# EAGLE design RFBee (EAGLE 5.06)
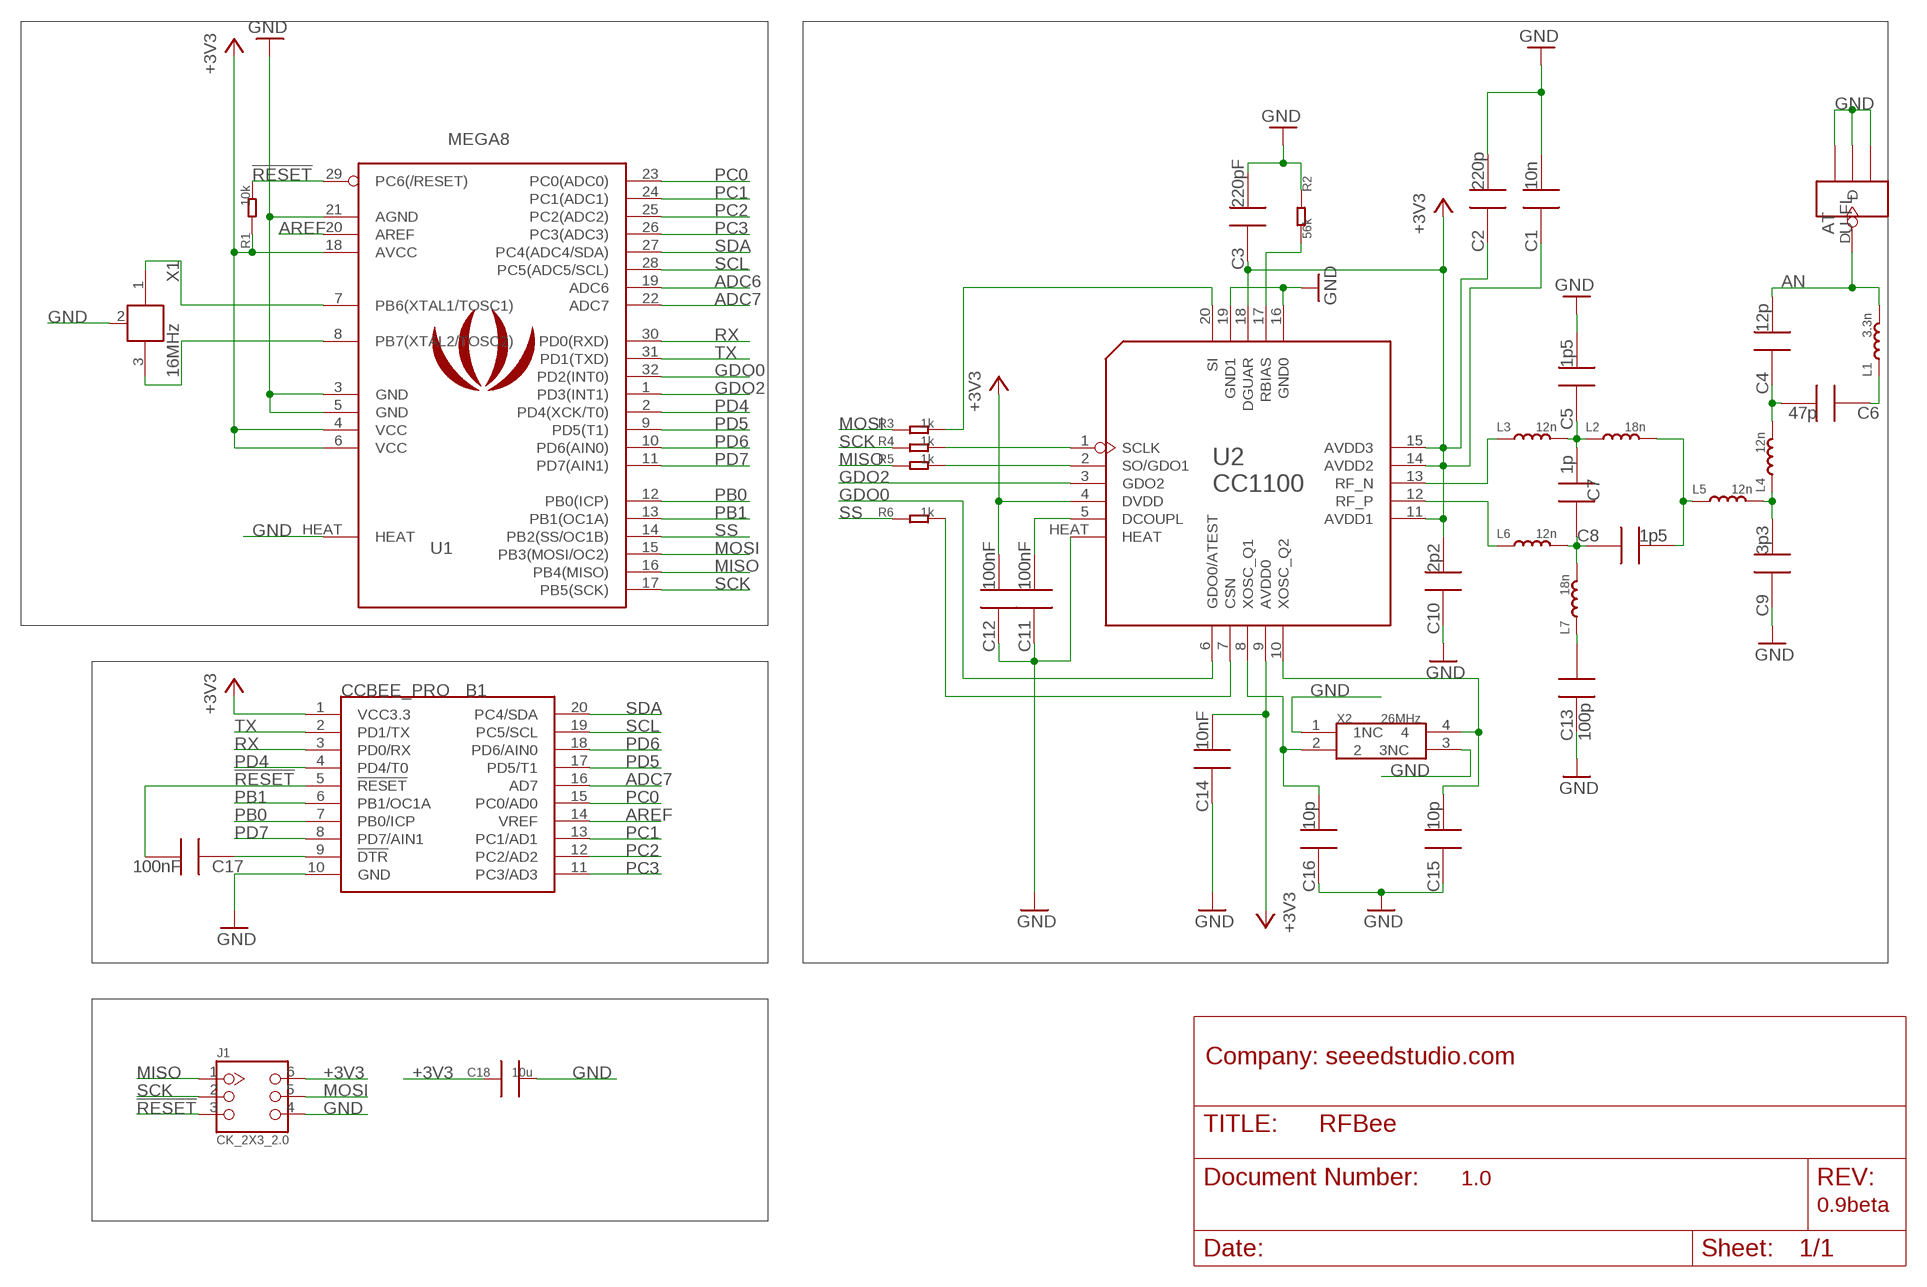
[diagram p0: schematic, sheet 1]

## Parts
AT  U-FL  [U-FL]
B1  CCBEE_PRO  [CCBEE-PRO]
C1  10n  C0603_S  [0603_S]
C2  220p  C0603_S  [0603_S]
C3  220pF  C0603_S  [0603_S]
C4  12p  C0603_S  [0603_S]
C5  1p5  C0603_S  [0603_S]
C6  47p  C0603_S  [0603_S]
C7  1p  C0603_S  [0603_S]
C8  1p5  C0603_S  [0603_S]
C9  3p3  C0603_S  [0603_S]
C10  2p2  C0603_S  [0603_S]
C11  100nF  C0603_S  [0603_S]
C12  100nF  C0603_S  [0603_S]
C13  100p  C0603_S  [0603_S]
C14  10nF  C0603_S  [0603_S]
C15  10p  C0603_S  [0603_S]
C16  10p  C0603_S  [0603_S]
C17  100nF  C0603_S  [0603_S]
C18  10u  C0805  [0805]
J1  CK_2X3_2.0  [CK_2X3_2.0]
L1  3.3n  L0603_S  [0603_S]
L2  18n  L0603_S  [0603_S]
L3  12n  L0603_S  [0603_S]
L4  12n  L0603_S  [0603_S]
L5  12n  L0603_S  [0603_S]
L6  12n  L0603_S  [0603_S]
L7  18n  L0603_S  [0603_S]
LOGO1  LOGO_SILK  [LOGO_SILK]
R1  10k  R0603_S  [0603_S]
R2  56k  R0603_S  [0603_S]
R3  1k  R0603_S  [0603_S]
R4  1k  R0603_S  [0603_S]
R5  1k  R0603_S  [0603_S]
R6  1k  R0603_S  [0603_S]
U1  MEGA8  [MLF32X]
U2  CC1100  [QFN20]
X1  16MHz  XTAL_NCVER  [XTAL_3X2]
X2  26MHz  XTAL_SMD_3225  [X3225]

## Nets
!RESET: B1.5(!RESET) C17.2 J1.3 R1.2 U1.29(PC6(/RESET))
+3V3: B1.1(VCC3.3) C1.1 C2.1 C3.1 C10.2 C12.2 C14.2 C18.1 J1.6 R1.1 U1.4(VCC) U1.6(VCC) U1.18(AVCC) U2.4(DVDD) U2.9(AVDD0) U2.11(AVDD1) U2.14(AVDD2) U2.15(AVDD3) U2.18(DGUAR)
ADC6: U1.19(ADC6)
ADC7: B1.16(AD7) U1.22(ADC7)
AN: AT.D C4.2 L1.2
AREF: B1.14(VREF) U1.20(AREF)
DTR: B1.9(!DTR) C17.1
GDO0: U1.32(PD2(INT0)) U2.6(GDO0/ATEST)
GDO2: U1.1(PD3(INT1)) U2.3(GDO2)
GND: AT.GND1 AT.GND2 AT.GND3 B1.10(GND) C1.2 C2.2 C3.2 C5.2 C9.1 C10.1 C11.1 C12.1 C13.1 C14.1 C15.1 C16.1 C18.2 J1.4 R2.1 U1.3(GND) U1.5(GND) U1.21(AGND) U1.HEAT U2.16(GND0) U2.19(GND1) U2.HEAT X1.2(GND) X2.1(1NC) X2.3(3NC)
MISO: J1.1 R5.1 U1.16(PB4(MISO))
MOSI: J1.5 R3.1 U1.15(PB3(MOSI/OC2))
N$1: C11.2 U2.5(DCOUPL)
N$2: C16.2 U2.8(XOSC_Q1) X2.2
N$3: R4.2 U2.1(SCLK)
N$4: L3.1 U2.13(RF_N)
N$5: L6.1 U2.12(RF_P)
N$6: C5.1 C7.2 L2.1 L3.2
N$7: C7.1 C8.1 L6.2 L7.2
N$8: C8.2 L2.2 L5.1
N$9: C9.2 L4.1 L5.2
N$10: C4.1 C6.2 L4.2
N$11: U1.7(PB6(XTAL1/TOSC1)) X1.1
N$12: C13.2 L7.1
N$13: U1.8(PB7(XTAL2/TOSC2)) X1.3
N$14: R3.2 U2.20(SI)
N$15: R2.2 U2.17(RBIAS)
N$16: C15.2 U2.10(XOSC_Q2) X2.4
N$17: R5.2 U2.2(SO/GDO1)
N$18: R6.2 U2.7(CSN)
N$21: C6.1 L1.1
PB0: B1.7(PB0/ICP) U1.12(PB0(ICP))
PB1: B1.6(PB1/OC1A) U1.13(PB1(OC1A))
PC0: B1.15(PC0/AD0) U1.23(PC0(ADC0))
PC1: B1.13(PC1/AD1) U1.24(PC1(ADC1))
PC2: B1.12(PC2/AD2) U1.25(PC2(ADC2))
PC3: B1.11(PC3/AD3) U1.26(PC3(ADC3))
PD4: B1.4(PD4/T0) U1.2(PD4(XCK/T0))
PD5: B1.17(PD5/T1) U1.9(PD5(T1))
PD6: B1.18(PD6/AIN0) U1.10(PD6(AIN0))
PD7: B1.8(PD7/AIN1) U1.11(PD7(AIN1))
RX: B1.3(PD0/RX) U1.30(PD0(RXD))
SCK: J1.2 R4.1 U1.17(PB5(SCK))
SCL: B1.19(PC5/SCL) U1.28(PC5(ADC5/SCL))
SDA: B1.20(PC4/SDA) U1.27(PC4(ADC4/SDA))
SS: R6.1 U1.14(PB2(SS/OC1B))
TX: B1.2(PD1/TX) U1.31(PD1(TXD))

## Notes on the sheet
- Company: seeedstudio.com
- 1.0
- 0.9beta

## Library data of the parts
AT = CPT_SMD:U-FL
B1 = EXT_moudle:CCBEE
C1-C17 = CPT_SMD:C0603
C18 = CPT_SMD:C0805
J1 = CONNECTER:CK_2X3
L1-L7 = CPT_SMD:L0603
LOGO1 = logo:LOGO_SILK
R1-R6 = CPT_SMD:R0603
U1 = ICs_v54:MEGA8
U2 = Wireless_chips:CC1100
X1 = CPT_SMD:XTAL_NC
X2 = CPT_SMD:XTAL_SMD

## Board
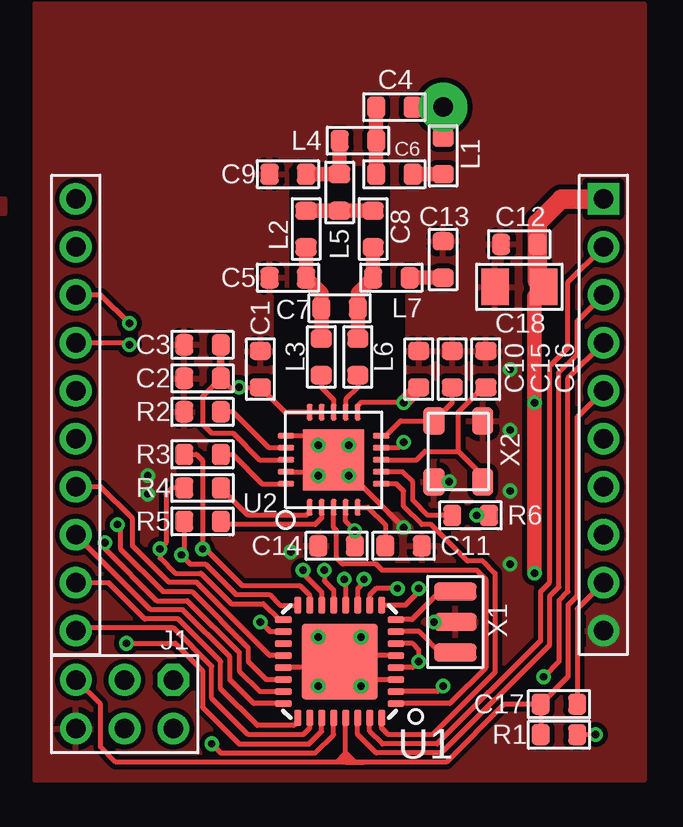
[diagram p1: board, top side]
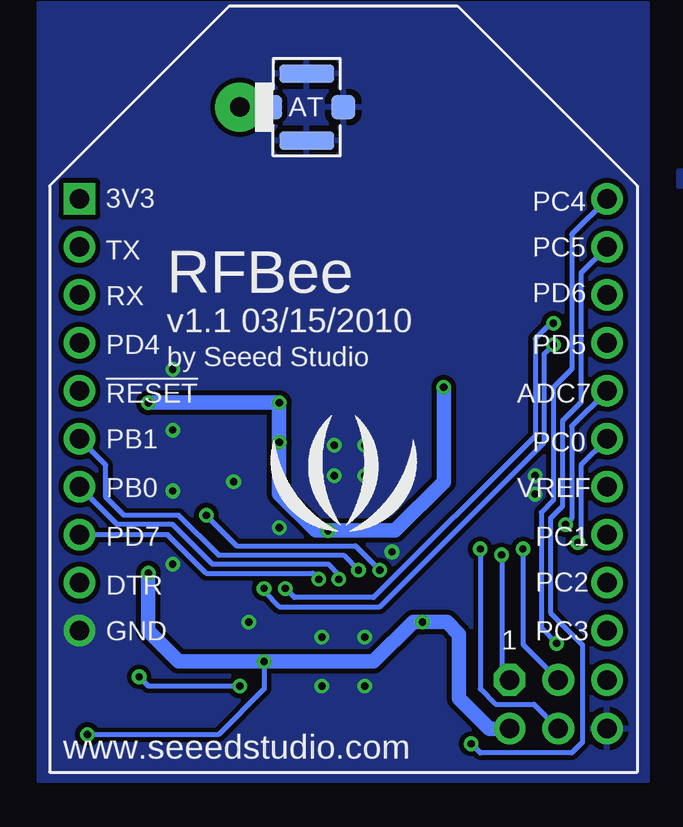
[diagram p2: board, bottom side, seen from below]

No outline drawn. Coordinates in mm, seen from the top.
Copper layers (1*16): Top 0.035mm / dielectric 1.5mm / Bottom 0.035mm
Design rules "SeeedStudio_rule_no_angle_090911 *": minimum track width 6mil, minimum drill 12mil, track to track 6mil, track to pad 6mil, pad to pad 6mil, via to via 6mil, smd to smd 0mil, copper to edge 3mil, drill to drill 10mil, minimum pad ring 10mil, minimum via ring 6mil, stop-mask expansion 2mil, vias tented up to drill 30mil, thermal gap 10mil
tRestrict: area -2.8,-13.1 to 2.8,-7.5; area -2.5,-3.8 to 2.5,5.1; area -1.9,5.1 to 1.9,10.2

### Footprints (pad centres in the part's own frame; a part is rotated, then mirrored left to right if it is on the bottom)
U-FL = smd 1.016 x 1.016: D -1.524,0; GND3 1.524,0 | smd 2.286 x 0.762: GND1 0,1.397; GND2 0,-1.397
CCBEE-PRO = drill 0.813 square: 1 -11,9 | drill 0.813 round: 2 -11,7; 3 -11,5; 4 -11,3; 5 -11,1; 6 -11,-1; 7 -11,-3; 8 -11,-5; 9 -11,-7; 10 -11,-9; 11 11,-9; 12 11,-7; 13 11,-5; 14 11,-3; 15 11,-1; 16 11,1; 17 11,3; 18 11,5; 19 11,7; 20 11,9
0603_S = smd 0.762 x 0.889: 1 -0.762,0; 2 0.762,0
0805 = smd 1.143 x 1.524: 1 -1.016,0; 2 1.016,0
CK_2X3_2.0 = drill 0.813 pad 1.27 octagon: 1 -1.016,2.032 | drill 0.813 pad 1.27 round: 2 -1.016,0; 3 -1.016,-2.032; 4 1.016,-2.032; 5 1.016,0; 6 1.016,2.032
MLF32X = smd 0.7 x 0.3: 1 -2.35,1.75; 2 -2.35,1.25; 3 -2.35,0.75; 4 -2.35,0.25; 5 -2.35,-0.25; 6 -2.35,-0.75; 7 -2.35,-1.25; 8 -2.35,-1.75; 17 2.35,-1.75; 18 2.35,-1.25; 19 2.35,-0.75; 20 2.35,-0.25; 21 2.35,0.25; 22 2.35,0.75; 23 2.35,1.25; 24 2.35,1.75 | smd 0.3 x 0.7: 9 -1.75,-2.35; 10 -1.25,-2.35; 11 -0.75,-2.35; 12 -0.25,-2.35; 13 0.25,-2.35; 14 0.75,-2.35; 15 1.25,-2.35; 16 1.75,-2.35; 25 1.75,2.35; 26 1.25,2.35; 27 0.75,2.35; 28 0.25,2.35; 29 -0.25,2.35; 30 -0.75,2.35; 31 -1.25,2.35; 32 -1.75,2.35 | smd 3.175 x 3.175: HEAT 0,0
QFN20 = smd 0.686 x 0.241: 1 -3.986,1.25; 2 -3.986,0.75; 3 -3.986,0.25; 4 -3.986,-0.25; 5 -3.986,-0.75; 11 -0.013,-0.75; 12 -0.013,-0.25; 13 -0.013,0.25; 14 -0.013,0.75; 15 -0.013,1.25 | smd 0.241 x 0.686: 6 -3,-1.736; 7 -2.5,-1.736; 8 -2,-1.736; 9 -1.5,-1.736; 10 -1,-1.736; 16 -1,2.236; 17 -1.5,2.236; 18 -2,2.236; 19 -2.5,2.236; 20 -3,2.236 | smd 2.54 x 2.54: HEAT -2,0.25
XTAL_3X2 = smd 0.762 x 1.778: 1 -1.27,0; 2 0,0; 3 1.27,0
X3225 = smd 1.143 x 0.889: 1 -1.27,1.016; 2 -1.27,-1.016; 3 1.27,-1.016; 4 1.27,1.016

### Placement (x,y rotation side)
AT  1.52,12.83 0 bottom
B1  0,0 0 bottom
C1  -3.3,1.91 90 top
C2  -5.71,1.52 180 top
C3  -5.71,2.92 180 top
C4  2.29,12.83 0 top
C5  -2.16,5.71 180 top
C6  2.29,10.03 180 top
C7  0,4.45 180 top
C8  1.4,7.75 90 top
C9  -2.16,10.03 0 top
C10  3.3,1.91 270 top
C11  2.67,-5.46 180 top
C12  7.49,7.11 0 top
C13  4.32,6.48 270 top
C14  -0.13,-5.46 0 top
C15  4.7,1.91 270 top
C16  6.1,1.91 270 top
C17  9.14,-12.06 180 top
C18  7.49,5.33 180 top
J1  -8.97,-12.06 270 top
L1  4.32,10.79 90 top
L2  -1.4,7.75 90 top
L3  -0.76,2.41 90 top
L4  0.76,11.43 0 top
L5  0,9.27 90 top
L6  0.76,2.41 90 top
L7  2.16,5.71 180 top
LOGO1  0,-3.17 0 bottom
R1  9.14,-13.34 180 top
R2  -5.71,0.13 0 top
R3  -5.71,-1.65 0 top
R4  -5.71,-3.05 0 top
R5  -5.71,-4.45 0 top
R6  5.46,-4.19 180 top
U1  0,-10.29 180 top
U2  0,0.13 90 top
X1  4.83,-8.64 90 top
X2  4.95,-1.52 90 top

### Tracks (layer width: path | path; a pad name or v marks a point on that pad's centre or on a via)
!RESET
  Top 0.203: J1.3 -9.97,-12.08 -9.97,-13.84 -9.34,-14.48 0.25,-14.48 | 0.25,-14.48 0.25,-14.47 | -0.25,-14.48 -0.13,-14.48 0.25,-14.1 | 0.25,-14.1 0.25,-14.22 | 0.25,-14.22 0.13,-14.35 0.38,-14.35 0.25,-14.48 | 0.25,-14.48 0.64,-14.48 | 0.64,-14.48 1.02,-14.48 | 0.64,-14.48 0.25,-14.1 | U1.29 0.25,-14.22 | 0.25,-14.48 4.45,-14.48 6.86,-12.06 C17.2 | B1.5 9.91,-0.09 9.91,-7.56 9.53,-7.94 9.53,-10.92 C17.2 | C17.2 R1.2
+3V3  (via drill 0.3)
  Top 0.203: U2.11 0.75,0.37 0.89,0.51 v2.67,0.51 | U2.18 -3.33,-1.87 -4.45,-0.76 -5.33,-0.76 -5.71,-0.38 -5.71,0.76 C2.1 -4.57,1.14 v-4.19,1.14 C1.1 -2.27,0.11 U2.15 U2.14 | U1.4 3.05,-10.54 v3.3,-10.28 3.3,-9.79 3.05,-9.54 U1.6 | U2.9 2.44,-1.37 v2.67,-1.14 | U2.4 0.25,-4.44 v0.64,-4.83 C14.2 | v10.67,-13.34 R1.1 | U1.18 -2.9,-9.04 v-3.3,-8.64
  Top 0.305: C3.1 C2.1
  Top 0.61: 8.26,5.59 C18.1 8.13,4.95 8.13,0.38 | v2.67,0.51 C10.2 | v8.13,0.51 8.13,0.38 | 8.13,0.38 v8.13,-6.6
  Top 0.813: B1.1 9.25,9 8.26,8 C12.2 8.26,5.59
  Bottom 0.203: v10.67,-13.34 5.21,-13.34 3.3,-11.43 v3.3,-10.28
  Bottom 0.61: v-4.19,1.14 -4.19,-2.79 -2.16,-4.83 v0.64,-4.83 1.14,-4.83 2.67,-3.3 v2.67,-1.14 v2.67,0.51 v8.13,0.51 | J1.6 -6.1,-13.08 -4.83,-11.81 -4.83,-9.14 -4.32,-8.64 v-3.3,-8.64 -2.92,-8.64 -1.27,-10.29 v3.3,-10.29 v3.3,-10.28 v3.31,-10.29 6.86,-10.29 8.13,-9.02 v8.13,-6.6
  pour Top: -14.61,9.02 -13.97,9.02 -13.97,8.38 -14.61,8.38
ADC7  (via drill 0.3)
  Top 0.203: v-9.27,-4.57 -9.14,-4.7 -9.14,-5.59 -7.37,-7.37 -6.16,-7.37 -3.81,-9.72 -3.81,-10.29 -3.06,-11.04 U1.22
  Bottom 0.203: v-9.27,-4.57 -9.53,-4.32 -9.53,-0.47 B1.16
AN  (via drill 0.81 pad 2.03)
  Top 0.61: 3.3,12.83 AT.D | L1.2 4.32,11.68
  Top 0.813: 3.3,12.83 v4.32,12.83 4.32,11.68
  Bottom 1.016: v4.32,12.83 AT.D
AREF
  Top 0.203: B1.14 -9.95,-3 -8.64,-4.32 -8.64,-5.46 -7.11,-6.99 -5.97,-6.99 -2.92,-10.04 U1.20
DTR
  Top 0.203: B1.9 9.91,-8.09 C17.1
GDO0
  Top 0.203: U2.6 2.37,-2.87 2.67,-3.17 2.67,-3.81 3.43,-4.57 3.81,-4.57 5.33,-6.1 5.97,-6.1 6.48,-6.6 6.48,-10.73 3.87,-13.34 2.03,-13.34 1.75,-13.05 U1.32
GDO2
  Top 0.203: U2.3 -0.25,-4.7 -0.13,-4.83 -0.13,-5.97 0.13,-6.22 1.52,-6.22 1.78,-6.48 5.71,-6.48 6.1,-6.86 6.1,-10.54 4.6,-12.04 U1.1
GND  (via drill 0.3)
  Top 0.203: U2.19 -0.75,-2.37 | -0.75,-2.37 U2.HEAT -1.25,-0.87 U2.16 | v-0.89,-2.54 -0.89,-2.51 -0.75,-2.37 | U1.21 -0.25,-10.54 U1.HEAT | U1.5 0.25,-10.04 U1.HEAT | U1.3 0.75,-11.04 U1.HEAT | v0.89,-11.3 0.89,-11.18 U1.HEAT | v0.89,-9.27 0.89,-9.4 U1.HEAT | v2.67,-4.7 0.51,-2.54 v0.38,-2.54
  other vias: 4.57,-2.79 -0.89,-1.27 0.38,-1.27 -2.03,-5.71 3.94,-8.64 -8,-2.54 -8,-3.3 -0.89,-11.3 -0.89,-9.27 7.11,-6.22 7.11,-3.17 7.11,-0.64 7.11,1.91
  pour Bottom: -14.61,10.16 -13.97,10.16 -13.97,9.53 -14.61,9.53
  pour Top (isolate 0.203, rank 6): -12.7,17.14 12.7,17.14 12.7,-15.24 -12.7,-15.24
  pour Bottom (isolate 0.203, rank 6): -12.7,17.14 12.7,17.14 12.7,-15.24 -12.7,-15.24
  pour Top (isolate 0.254, no thermals): 9.53,-8.26 12.45,-8.26 12.45,-10.16 9.53,-10.16
  pour Bottom (isolate 0.203, no thermals): 9.53,-8.26 12.45,-8.26 12.45,-10.16 9.53,-10.16
MISO  (via drill 0.3)
  Top 0.203: R5.1 -6.48,-5.71 v-6.6,-5.84 -6.22,-6.22 -5.59,-6.22 -4.32,-7.49 -2.92,-7.49 -2.48,-7.94 U1.16
  Bottom 0.203: J1.1 -6.6,-10.72 v-6.6,-5.84
MOSI  (via drill 0.3)
  Top 0.203: R3.1 -5.97,-1.65 -5.71,-1.91 v-5.71,-5.59 -5.59,-5.59 -4.06,-7.11 -1.65,-7.11 -1.25,-7.51 U1.15
  Bottom 0.203: J1.5 -7.95,-12.06 -6.35,-12.06 -5.71,-11.43 v-5.71,-5.59
N$1
  Top 0.203: U2.5 1.19,-3.86 1.91,-4.57 C11.2
N$2
  Top 0.203: U2.8 3.21,-1.87 3.56,-1.52 4.95,-1.52 | X2.2 5.97,-2.54 4.95,-1.52 | C16.2 5.97,1.14 4.95,0.13 4.95,-1.52
N$3
  Top 0.203: U2.1 -1.25,-4.04 -1.4,-4.19 -3.81,-4.19 R4.2
N$4
  Top 0.203: U2.13 -0.25,0.63 -0.76,1.14 L3.1
N$5
  Top 0.203: U2.12 0.25,0.63 0.76,1.14 L6.1
N$6
  Top 0.61: L3.2 C7.2 -0.76,5.08 C5.1 L2.1
N$7
  Top 0.61: L6.2 C7.1 0.76,5.08 L7.2 C8.1
N$8
  Top 0.61: L2.2 L5.1 C8.2
N$9
  Top 0.61: C9.2 L5.2 L4.1
N$10
  Top 0.61: C6.2 L4.2 C4.1
N$11
  Top 0.203: U1.7 3.32,-9.04 4.19,-9.91 X1.1
N$12
  Top 0.61: C13.2 L7.1
N$13
  Top 0.203: U1.8 3.02,-8.54 4.19,-7.37 X1.3
N$14
  Top 0.203: U2.20 -3.22,-2.87 -4.45,-1.65 R3.2
N$15
  Top 0.203: U2.17 -2.94,-1.37 -4.45,0.13 R2.2
N$16
  Top 0.203: C15.2 4.7,0.51 X2.4 2.54,-0.25 1.92,-0.87 U2.10
N$17
  Top 0.203: U2.2 -0.75,-4.31 -1.02,-4.57 -4.83,-4.57 R5.2
N$18
  Top 0.203: U2.7 2.63,-2.37 3.05,-2.79 3.05,-3.56 3.68,-4.19 R6.2
N$21
  Top 0.61: L1.1 C6.1
PB0  (via drill 0.3)
  Top 0.203: U1.12 0.25,-6.92 v0.19,-6.86
  Bottom 0.203: v0.19,-6.86 0.19,-6.67 0.64,-6.22 5.46,-6.22 7.11,-4.57 9.43,-4.57 B1.7
PB1  (via drill 0.3)
  Top 0.203: U1.13 -0.25,-7.31 -0.64,-6.92 v-0.64,-6.48
  Bottom 0.203: v-0.64,-6.48 0,-5.84 5.21,-5.84 6.86,-4.19 9.14,-4.19 9.91,-3.43 9.91,-2.09 B1.6
PC0  (via drill 0.3)
  Top 0.203: v-9.78,-5.33 -9.78,-5.59 -7.62,-7.75 -6.35,-7.75 -4.19,-9.91 -4.19,-10.67 -3.32,-11.54 U1.23
  Bottom 0.203: v-9.78,-5.33 -9.91,-5.21 -9.91,-2.09 B1.15
PC1
  Top 0.203: B1.13 -7.87,-8.13 -6.54,-8.13 -4.57,-10.1 -4.57,-11.05 -3.58,-12.04 U1.24
PC2
  Top 0.203: U1.25 -1.75,-12.8 -1.91,-12.95 -3.43,-12.95 -4.95,-11.43 -4.95,-10.29 -6.73,-8.51 -8.13,-8.51 -9.64,-7 B1.12
PC3
  Top 0.203: U1.26 -1.25,-13.06 -1.52,-13.34 -3.81,-13.34 -5.33,-11.81 -5.33,-10.48 -6.92,-8.89 -10.89,-8.89 B1.11
PD4  (via drill 0.3)
  Top 0.203: U1.2 4.08,-11.54 v4.32,-11.3 | B1.4 9.53,1.52 9.53,-7.37 9.14,-7.75 9.14,-10.29 v8.51,-10.92
  Bottom 0.203: v4.32,-11.3 8.13,-11.3 v8.51,-10.92
PD5  (via drill 0.3)
  Top 0.203: B1.17 -8.84,3 v-8.76,2.92 | U1.9 2.73,-7.94 3.3,-7.37 v3.3,-7.24
  Bottom 0.203: v-8.76,2.92 -8.38,2.54 -8.38,-1.14 -1.52,-8 2.67,-8 3.3,-7.37 v3.3,-7.24
PD6  (via drill 0.3)
  Top 0.203: B1.18 -9.95,5 v-8.76,3.81 | U1.10 1.25,-7.51 1.52,-7.24 v2.41,-7.24
  Bottom 0.203: v-8.76,3.81 -8.64,3.81 -8,3.17 -8,-0.89 -1.27,-7.62 2.03,-7.62 v2.41,-7.24
PD7  (via drill 0.3)
  Top 0.203: U1.11 0.75,-7.25 1.02,-6.99 v1.02,-6.86
  Bottom 0.203: v1.02,-6.86 1.27,-6.6 5.71,-6.6 7.32,-5 B1.8
RX
  Top 0.203: U1.30 0.75,-13.32 1.52,-14.1 4.25,-14.1 8.76,-9.59 8.76,-7.56 9.14,-7.18 9.14,1.78 9.91,2.54 9.91,3.91 B1.3
SCK  (via drill 0.3)
  Top 0.203: R4.1 -6.99,-3.05 -7.24,-3.3 -7.24,-5.33 v-7.49,-5.59 -7.49,-5.97 -6.86,-6.6 -5.78,-6.6 -4.51,-7.87 -3.17,-7.87 -2.51,-8.54 U1.17
  Bottom 0.203: J1.2 -7.49,-9.58 v-7.49,-5.59
SCL  (via drill 0.3)
  Top 0.203: U1.28 -0.25,-13.33 -1.02,-14.1 -4.95,-14.1 v-5.33,-13.72
  Bottom 0.203: B1.19 -9.91,5.91 -9.91,0.51 -9.14,-0.25 -9.14,-3.81 -8.64,-4.32 -8.64,-8.26 -9.97,-9.59 -9.97,-13.65 -9.53,-14.1 -5.71,-14.1 v-5.33,-13.72
SDA  (via drill 0.3)
  Top 0.203: U1.27 -0.75,-13.2 -1.27,-13.72 -4.19,-13.72 -5.71,-12.19 -5.71,-10.67 -6.86,-9.53 v-8.89,-9.53
  Bottom 0.203: v-8.89,-9.53 -8.26,-8.89 -8.26,-4.06 -8.76,-3.56 -8.76,1.14 -9.53,1.91 -9.53,7.53 B1.20
SS  (via drill 0.3)
  Top 0.203: U1.14 -0.75,-7.38 -1.52,-6.6 v-1.52,-6.48 | R6.1 v5.71,-4.19
  Bottom 0.203: v-1.52,-6.48 -0.51,-5.46 4.45,-5.46 v5.71,-4.19
TX
  Top 0.203: U1.31 1.25,-13.19 1.78,-13.72 4.06,-13.72 8.38,-9.4 8.38,-7.37 8.76,-6.99 8.76,2.03 9.53,2.79 9.53,5.53 B1.2

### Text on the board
bPlace: PC4 | 3V3 | PC5 | TX | PD6 | RFBee | RX | PD5 | v1.1 03/15/2010 | PD4 | by Seeed Studio | ADC7 | !RESET | PB1 | PC0 | VREF | PB0 | PC1 | PD7 | PC2 | DTR | PC3 | GND | 1 | www.seeedstudio.com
